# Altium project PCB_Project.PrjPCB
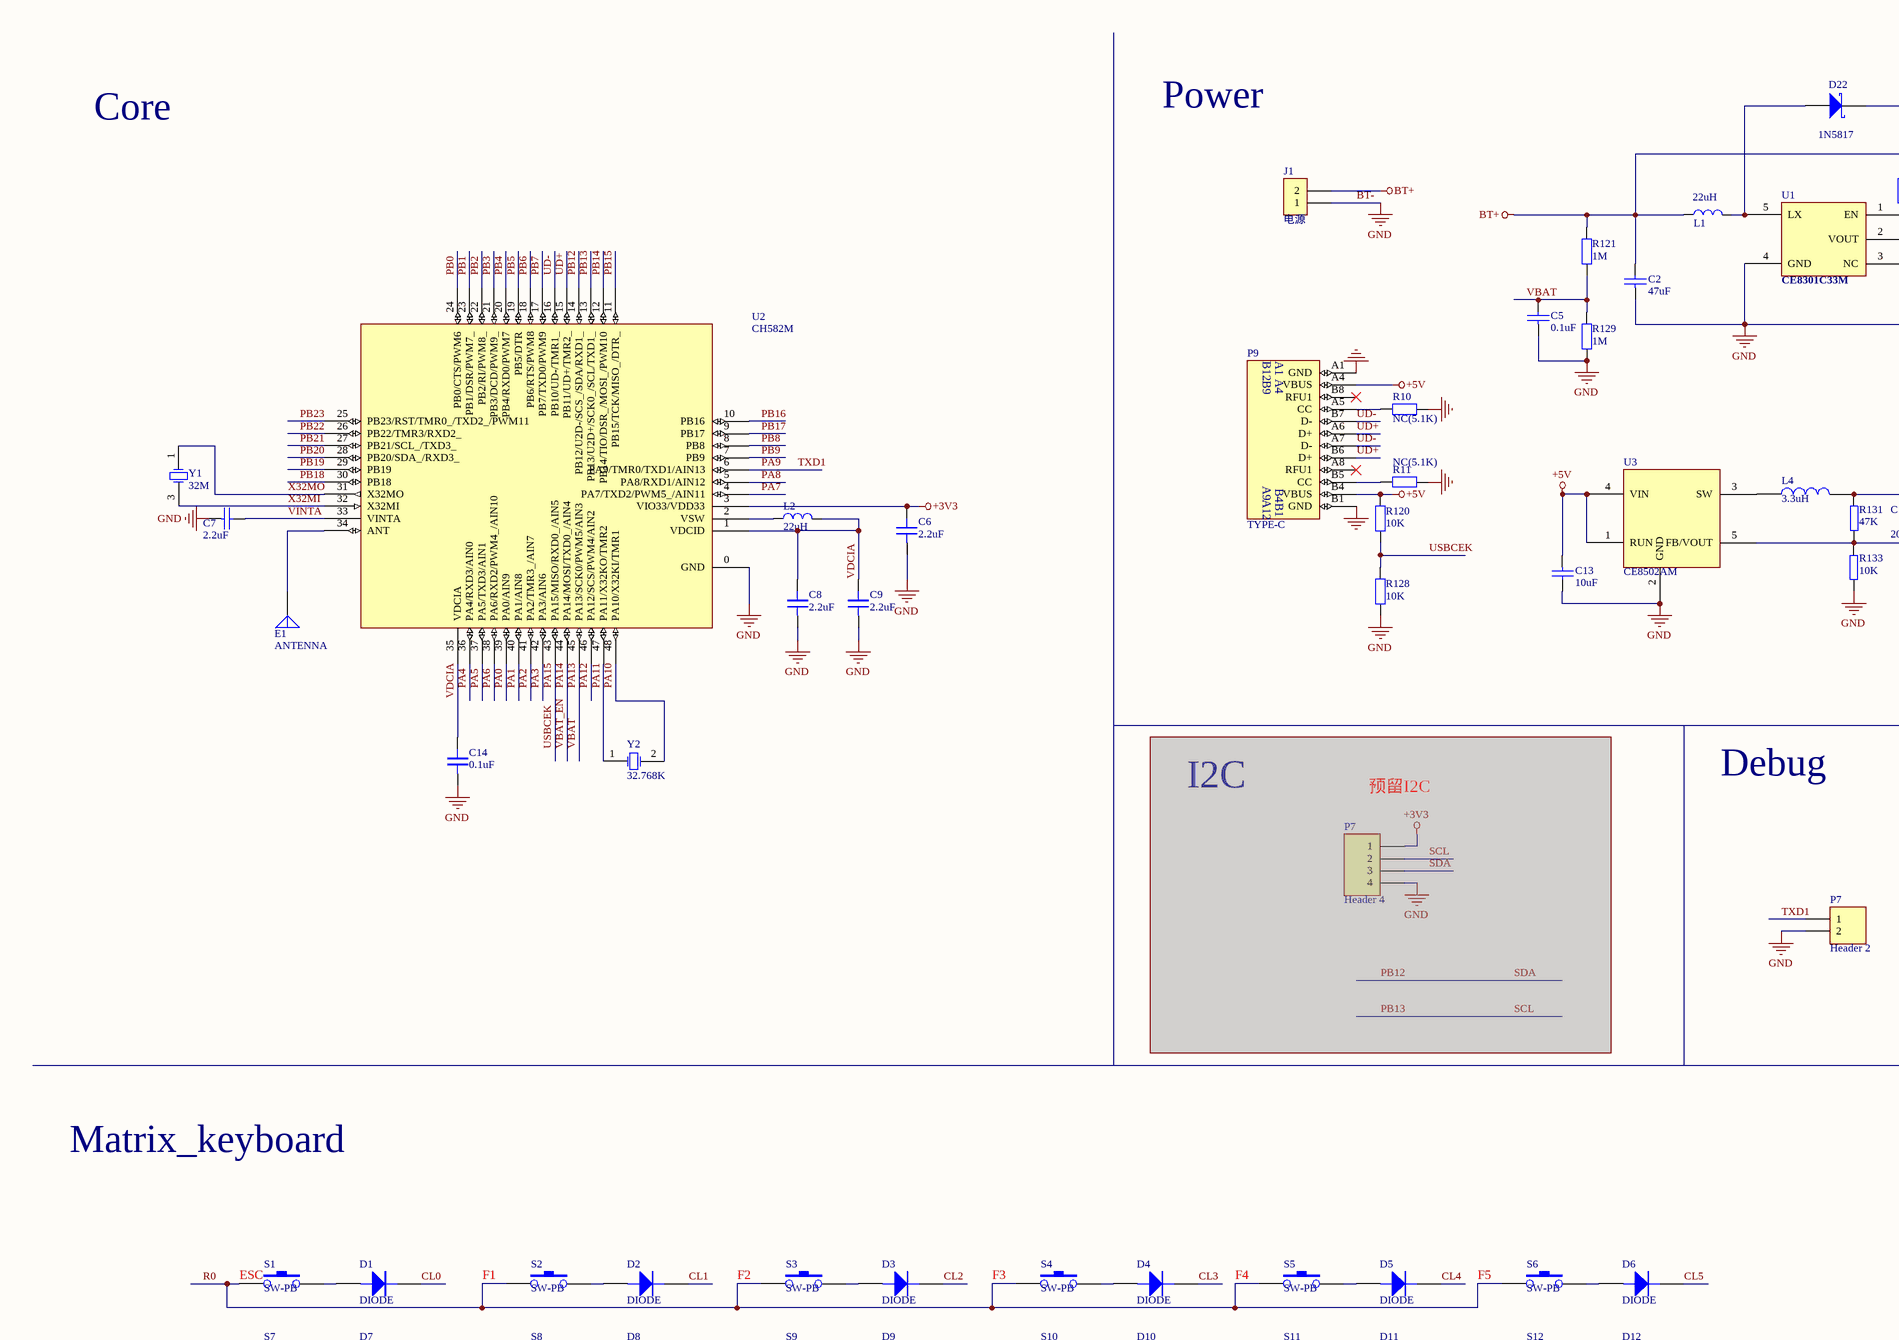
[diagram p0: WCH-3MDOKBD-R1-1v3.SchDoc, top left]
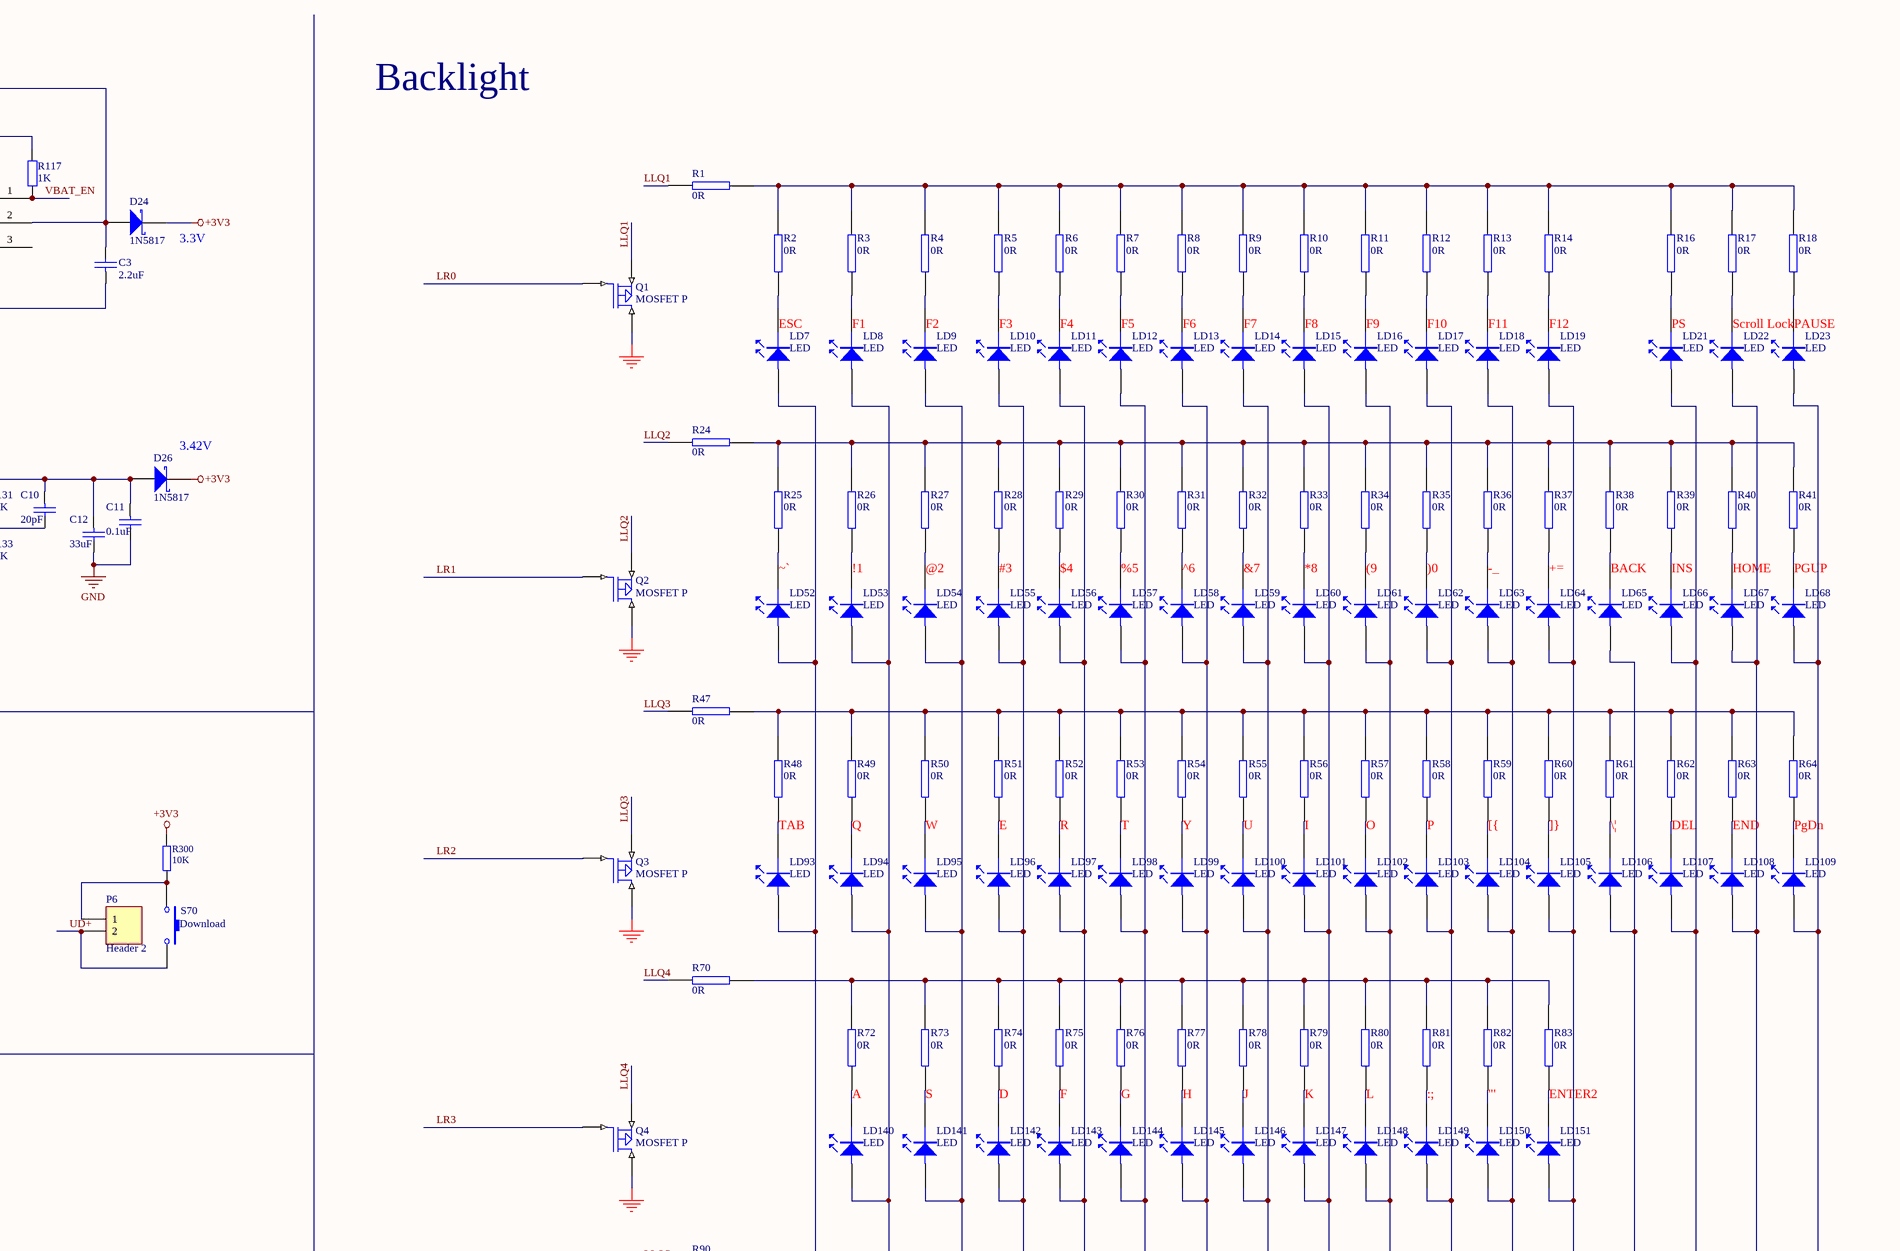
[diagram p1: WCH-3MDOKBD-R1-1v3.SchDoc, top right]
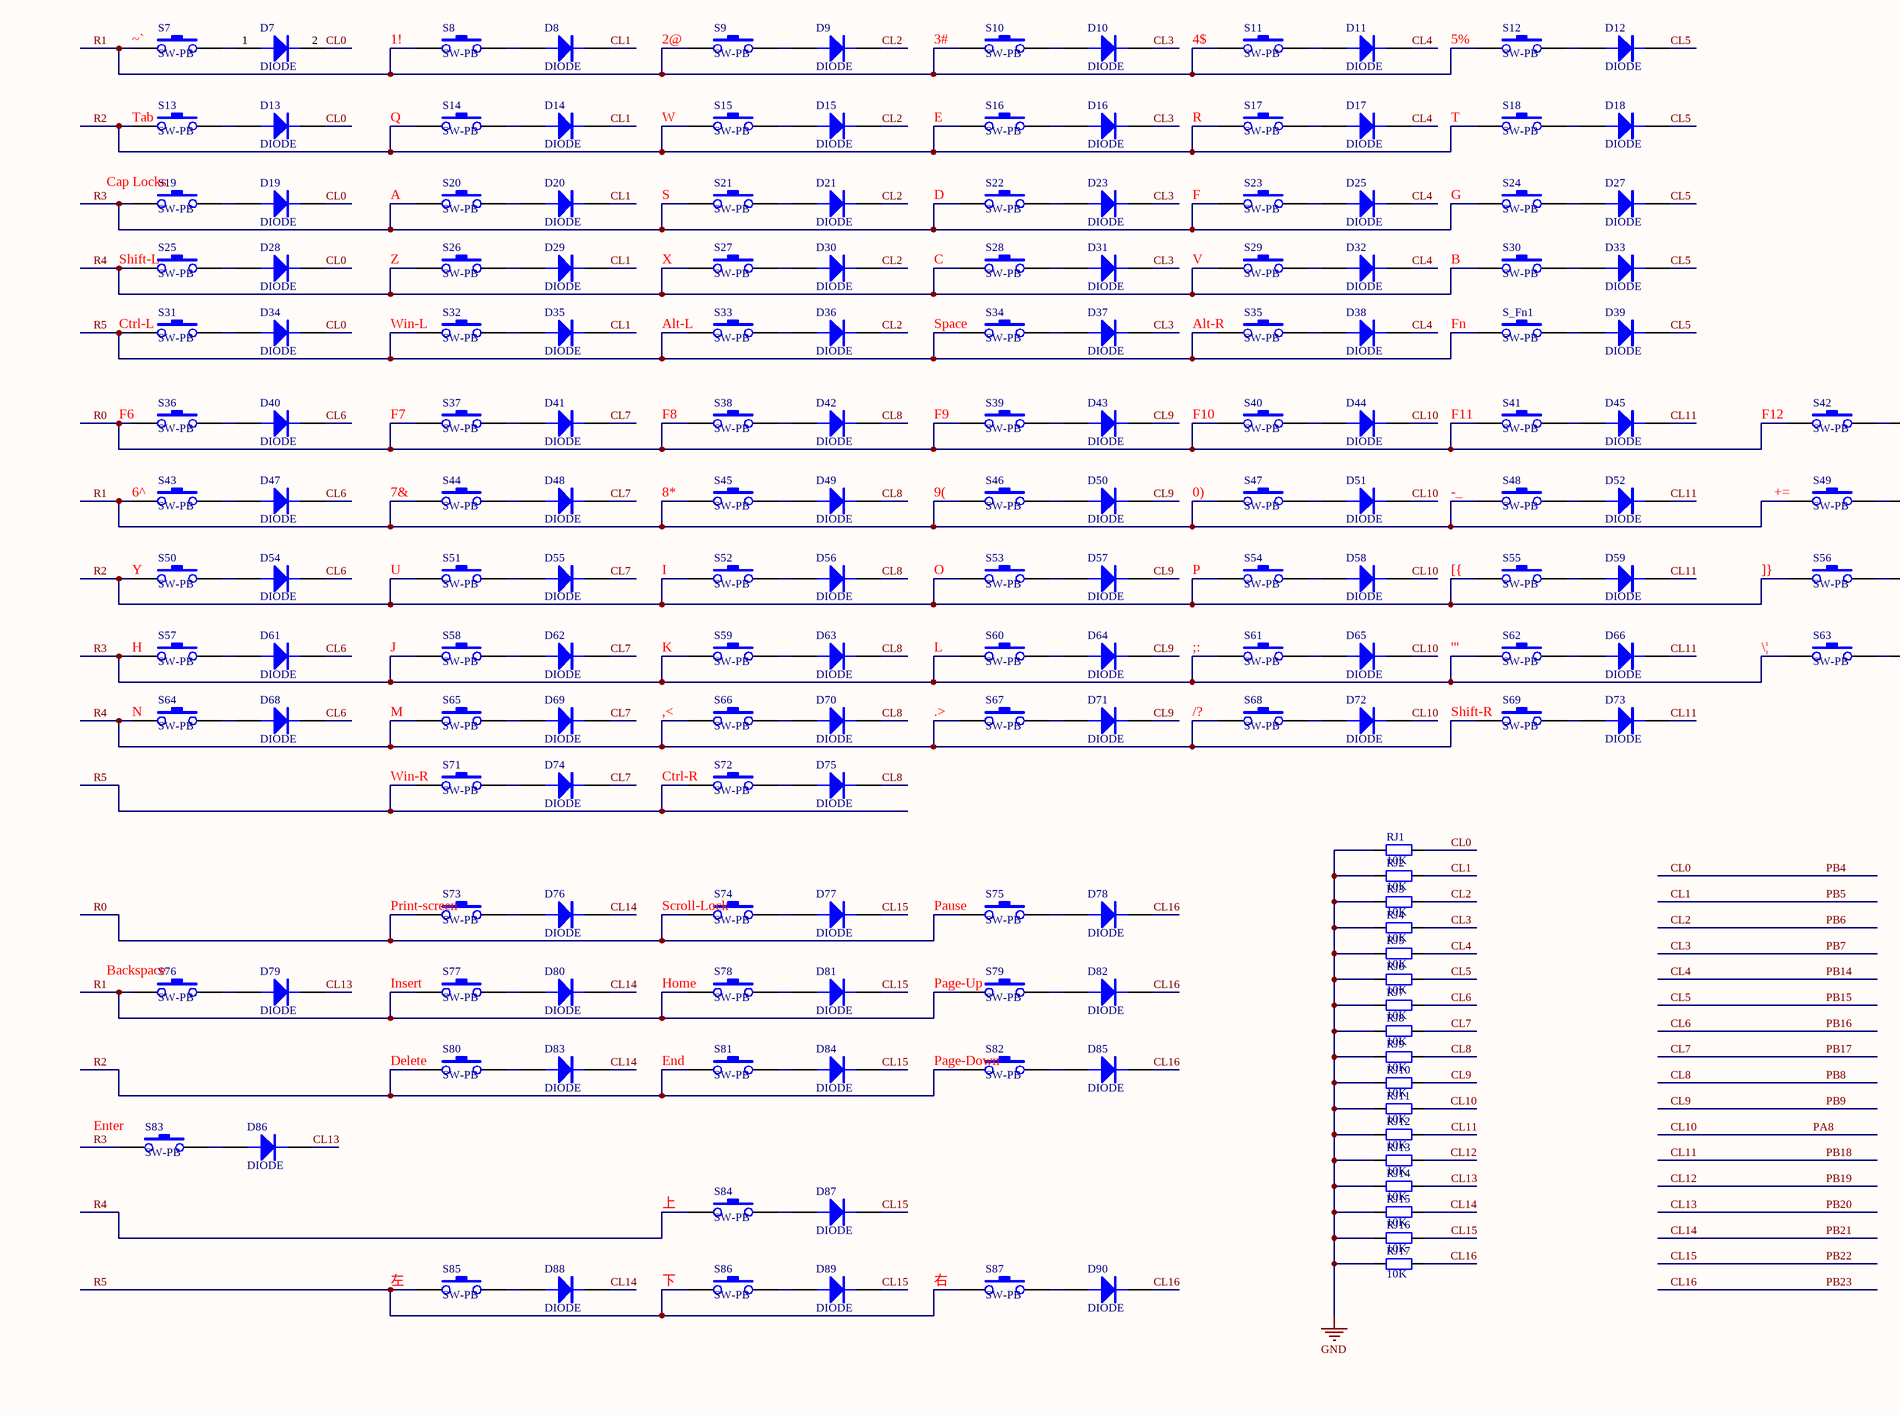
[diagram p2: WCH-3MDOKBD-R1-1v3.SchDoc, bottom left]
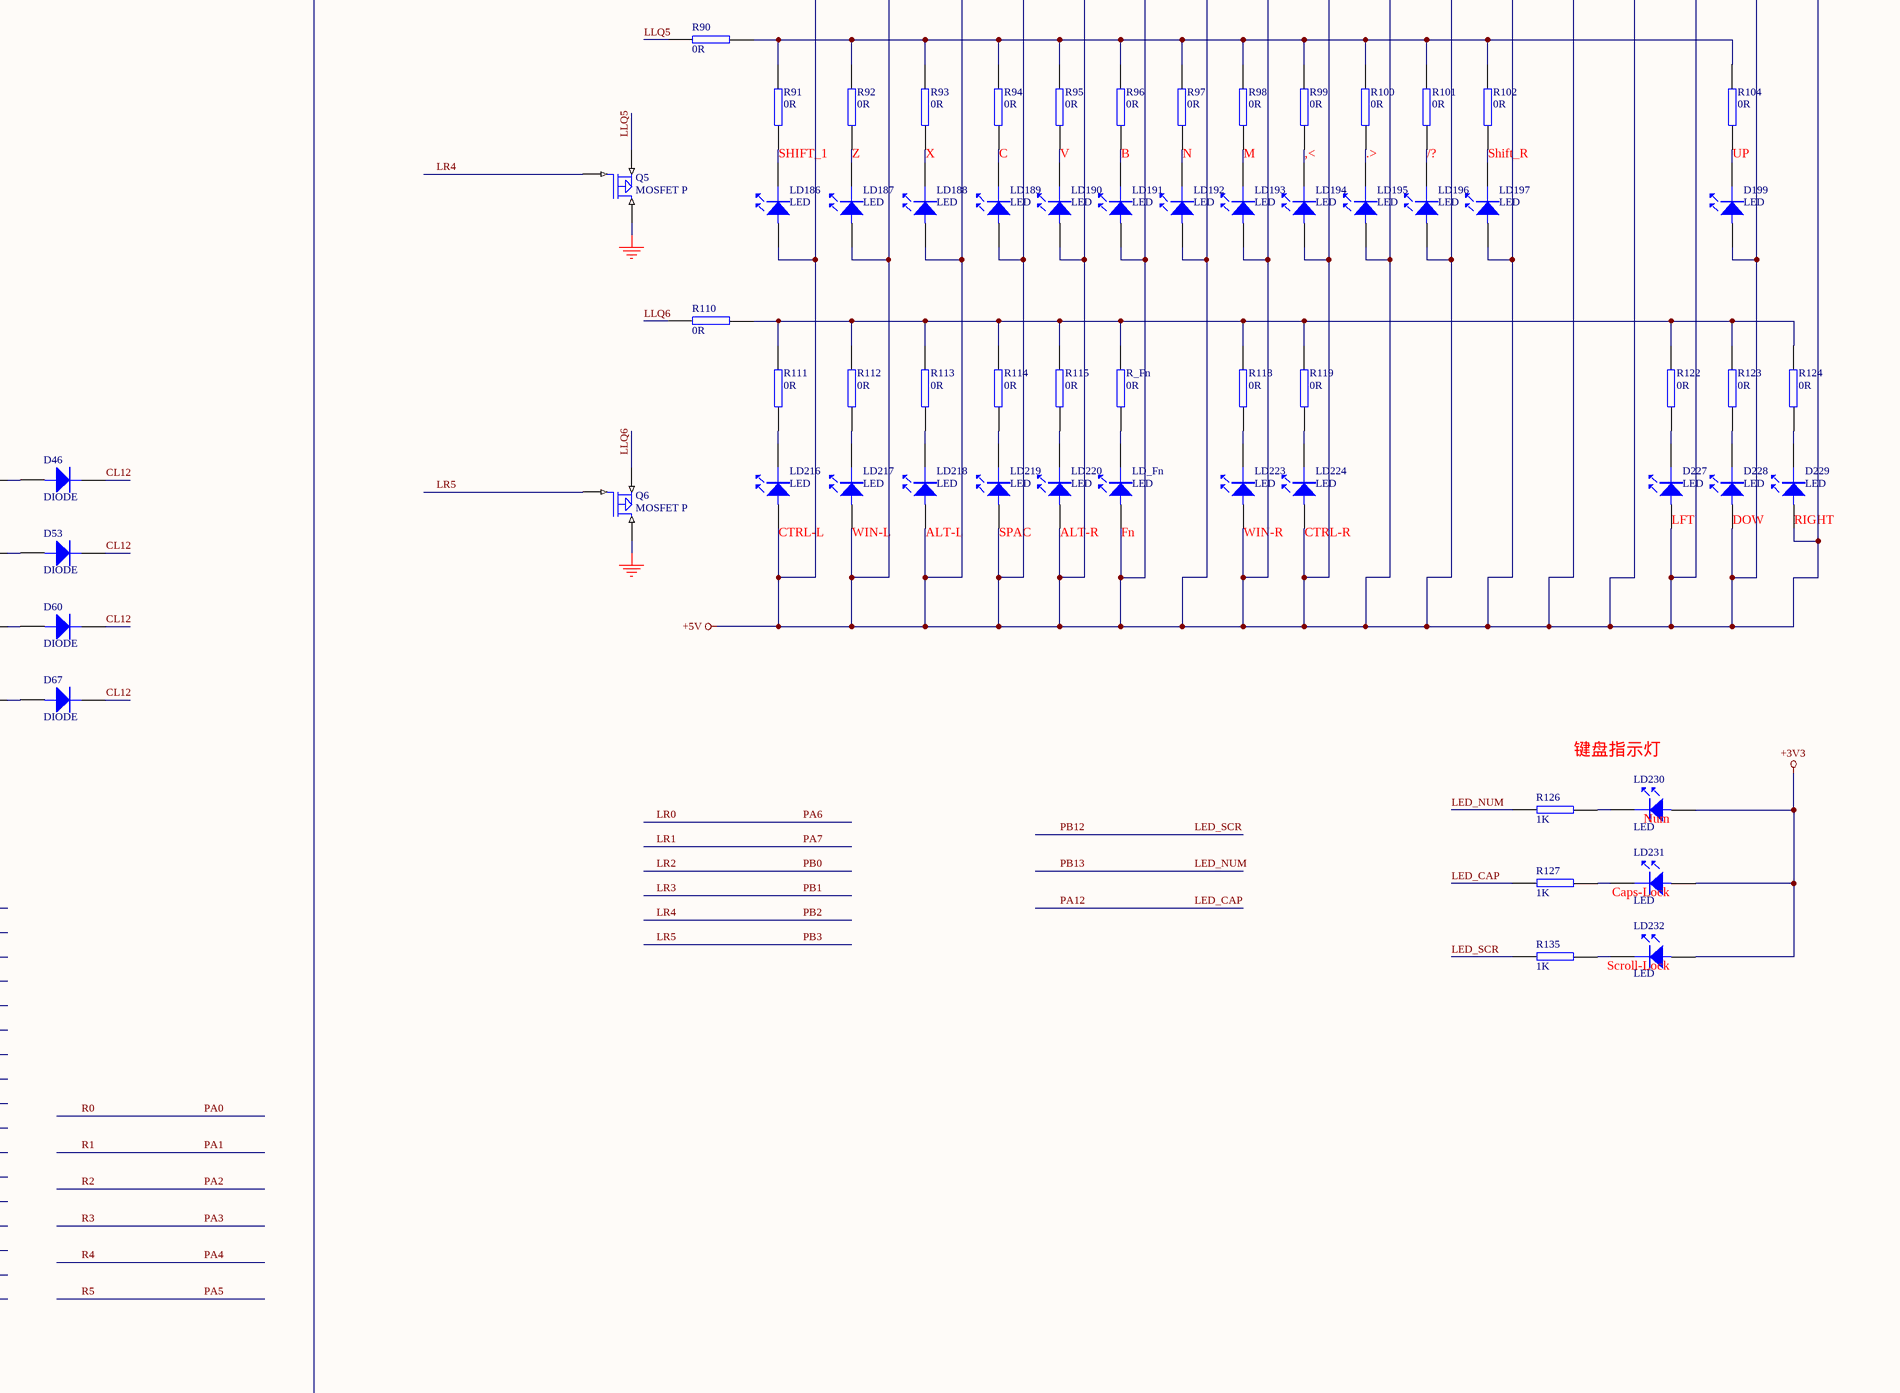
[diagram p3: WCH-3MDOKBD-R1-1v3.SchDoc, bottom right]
1 sheet, 421 parts. Net scope: global (net labels, ports and power ports of the same name join across sheets).
Board file: WCH-3MDOKBD-R1-1v3.PcbDoc

## Sheet WCH-3MDOKBD-R1-1v3.SchDoc
size A1

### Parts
(Parts that share a designator on the sheet are numbered #1, #2 ... from top to bottom, then left to right.)
C2  47uF  [3528_C]
C3  2.2uF  [0402_C]
C5  0.1uF  [0402_C]
C6  2.2uF  [0603_C]
C7  2.2uF  [0402_C]
C8  2.2uF  [0603_C]
C9  2.2uF  [0603_C]
C10  20pF  [0603_C]
C11  0.1uF  [0603_C]
C12  33uF  [3528_C]
C13  10uF  [3216_C]
C14  0.1uF  [0603_C]
D1  DIODE  [3216+]
D2  DIODE  [3216+]
D3  DIODE  [3216+]
D4  DIODE  [3216+]
D5  DIODE  [3216+]
D6  DIODE  [3216+]
D7  DIODE  [3216+]
D8  DIODE  [3216+]
D9  DIODE  [3216+]
D10  DIODE  [3216+]
D11  DIODE  [3216+]
D12  DIODE  [3216+]
D13  DIODE  [3216+]
D14  DIODE  [3216+]
D15  DIODE  [3216+]
D16  DIODE  [3216+]
D17  DIODE  [3216+]
D18  DIODE  [3216+]
D19  DIODE  [3216+]
D20  DIODE  [3216+]
D21  DIODE  [3216+]
D22  1N5817  [7227+]
D23  DIODE  [3216+]
D24  1N5817  [7227+]
D25  DIODE  [3216+]
D26  1N5817  [7227+]
D27  DIODE  [3216+]
D28  DIODE  [3216+]
D29  DIODE  [3216+]
D30  DIODE  [3216+]
D31  DIODE  [3216+]
D32  DIODE  [3216+]
D33  DIODE  [3216+]
D34  DIODE  [3216+]
D35  DIODE  [3216+]
D36  DIODE  [3216+]
D37  DIODE  [3216+]
D38  DIODE  [3216+]
D39  DIODE  [3216+]
D40  DIODE  [3216+]
D41  DIODE  [3216+]
D42  DIODE  [3216+]
D43  DIODE  [3216+]
D44  DIODE  [3216+]
D45  DIODE  [3216+]
D46  DIODE  [3216+]
D47  DIODE  [3216+]
D48  DIODE  [3216+]
D49  DIODE  [3216+]
D50  DIODE  [3216+]
D51  DIODE  [3216+]
D52  DIODE  [3216+]
D53  DIODE  [3216+]
D54  DIODE  [3216+]
D55  DIODE  [3216+]
D56  DIODE  [3216+]
D57  DIODE  [3216+]
D58  DIODE  [3216+]
D59  DIODE  [3216+]
D60  DIODE  [3216+]
D61  DIODE  [3216+]
D62  DIODE  [3216+]
D63  DIODE  [3216+]
D64  DIODE  [3216+]
D65  DIODE  [3216+]
D66  DIODE  [3216+]
D67  DIODE  [3216+]
D68  DIODE  [3216+]
D69  DIODE  [3216+]
D70  DIODE  [3216+]
D71  DIODE  [3216+]
D72  DIODE  [3216+]
D73  DIODE  [3216+]
D74  DIODE  [3216+]
D75  DIODE  [3216+]
D76  DIODE  [3216+]
D77  DIODE  [3216+]
D78  DIODE  [3216+]
D79  DIODE  [3216+]
D80  DIODE  [3216+]
D81  DIODE  [3216+]
D82  DIODE  [3216+]
D83  DIODE  [3216+]
D84  DIODE  [3216+]
D85  DIODE  [3216+]
D86  DIODE  [3216+]
D87  DIODE  [3216+]
D88  DIODE  [3216+]
D89  DIODE  [3216+]
D90  DIODE  [3216+]
D199  LED  [0603+]
D227  LED  [0603+]
D228  LED  [0603+]
D229  LED  [0603+]
E1  ANTENNA  [ANT-F-1-2.4G-1.6]
J1  电源  [SIP2-2.54mm]
L1  22uH  [SMD_7.3x7.8mm]
L2  22uH  [SMD_2x2mm]
L4  3.3uH  [SMD_5x5mm]
LD7  LED  [0603+]
LD8  LED  [0603+]
LD9  LED  [0603+]
LD10  LED  [0603+]
LD11  LED  [0603+]
LD12  LED  [0603+]
LD13  LED  [0603+]
LD14  LED  [0603+]
LD15  LED  [0603+]
LD16  LED  [0603+]
LD17  LED  [0603+]
LD18  LED  [0603+]
LD19  LED  [0603+]
LD21  LED  [0603+]
LD22  LED  [0603+]
LD23  LED  [0603+]
LD52  LED  [0603+]
LD53  LED  [0603+]
LD54  LED  [0603+]
LD55  LED  [0603+]
LD56  LED  [0603+]
LD57  LED  [0603+]
LD58  LED  [0603+]
LD59  LED  [0603+]
LD60  LED  [0603+]
LD61  LED  [0603+]
LD62  LED  [0603+]
LD63  LED  [0603+]
LD64  LED  [0603+]
LD65  LED  [0603+]
LD66  LED  [0603+]
LD67  LED  [0603+]
LD68  LED  [0603+]
LD93  LED  [0603+]
LD94  LED  [0603+]
LD95  LED  [0603+]
LD96  LED  [0603+]
LD97  LED  [0603+]
LD98  LED  [0603+]
LD99  LED  [0603+]
LD100  LED  [0603+]
LD101  LED  [0603+]
LD102  LED  [0603+]
LD103  LED  [0603+]
LD104  LED  [0603+]
LD105  LED  [0603+]
LD106  LED  [0603+]
LD107  LED  [0603+]
LD108  LED  [0603+]
LD109  LED  [0603+]
LD140  LED  [0603+]
LD141  LED  [0603+]
LD142  LED  [0603+]
LD143  LED  [0603+]
LD144  LED  [0603+]
LD145  LED  [0603+]
LD146  LED  [0603+]
LD147  LED  [0603+]
LD148  LED  [0603+]
LD149  LED  [0603+]
LD150  LED  [0603+]
LD151  LED  [0603+]
LD186  LED  [0603+]
LD187  LED  [0603+]
LD188  LED  [0603+]
LD189  LED  [0603+]
LD190  LED  [0603+]
LD191  LED  [0603+]
LD192  LED  [0603+]
LD193  LED  [0603+]
LD194  LED  [0603+]
LD195  LED  [0603+]
LD196  LED  [0603+]
LD197  LED  [0603+]
LD216  LED  [0603+]
LD217  LED  [0603+]
LD218  LED  [0603+]
LD219  LED  [0603+]
LD220  LED  [0603+]
LD223  LED  [0603+]
LD224  LED  [0603+]
LD230  LED  [0603+]
LD231  LED  [0603+]
LD232  LED  [0603+]
LD_Fn  LED  [0603+]
P6  Header 2  [SIP2-2.54mm]
P7#1  Header 4  [HDR1X4]  (masked out: inside a compile mask, not in the netlist)
P7#2  Header 2  [SIP2-2.54mm]
P9  TYPE-C  [TYPE-C-Receptacle-2.0]
Q1  MOSFET P  [SOT-23]
Q2  MOSFET P  [SOT-23]
Q3  MOSFET P  [SOT-23]
Q4  MOSFET P  [SOT-23]
Q5  MOSFET P  [SOT-23]
Q6  MOSFET P  [SOT-23]
R1  0R  [0603]
R2  0R  [0603]
R3  0R  [0603]
R4  0R  [0603]
R5  0R  [0603]
R6  0R  [0603]
R7  0R  [0603]
R8  0R  [0603]
R9  0R  [0603]
R10#1  0R  [0603]
R10#2  NC(5.1K)  [0603]
R11#1  0R  [0603]
R11#2  NC(5.1K)  [0603]
R12  0R  [0603]
R13  0R  [0603]
R14  0R  [0603]
R16  0R  [0603]
R17  0R  [0603]
R18  0R  [0603]
R24  0R  [0603]
R25  0R  [0603]
R26  0R  [0603]
R27  0R  [0603]
R28  0R  [0603]
R29  0R  [0603]
R30  0R  [0603]
R31  0R  [0603]
R32  0R  [0603]
R33  0R  [0603]
R34  0R  [0603]
R35  0R  [0603]
R36  0R  [0603]
R37  0R  [0603]
R38  0R  [0603]
R39  0R  [0603]
R40  0R  [0603]
R41  0R  [0603]
R47  0R  [0603]
R48  0R  [0603]
R49  0R  [0603]
R50  0R  [0603]
R51  0R  [0603]
R52  0R  [0603]
R53  0R  [0603]
R54  0R  [0603]
R55  0R  [0603]
R56  0R  [0603]
R57  0R  [0603]
R58  0R  [0603]
R59  0R  [0603]
R60  0R  [0603]
R61  0R  [0603]
R62  0R  [0603]
R63  0R  [0603]
R64  0R  [0603]
R70  0R  [0603]
R72  0R  [0603]
R73  0R  [0603]
R74  0R  [0603]
R75  0R  [0603]
R76  0R  [0603]
R77  0R  [0603]
R78  0R  [0603]
R79  0R  [0603]
R80  0R  [0603]
R81  0R  [0603]
R82  0R  [0603]
R83  0R  [0603]
R90  0R  [0603]
R91  0R  [0603]
R92  0R  [0603]
R93  0R  [0603]
R94  0R  [0603]
R95  0R  [0603]
R96  0R  [0603]
R97  0R  [0603]
R98  0R  [0603]
R99  0R  [0603]
R100  0R  [0603]
R101  0R  [0603]
R102  0R  [0603]
R104  0R  [0603]
R110  0R  [0603]
R111  0R  [0603]
R112  0R  [0603]
R113  0R  [0603]
R114  0R  [0603]
R115  0R  [0603]
R117  1K  [0603]
R118  0R  [0603]
R119  0R  [0603]
R120  10K  [0603]
R121  1M  [0603]
R122  0R  [0603]
R123  0R  [0603]
R124  0R  [0603]
R126  1K  [0603]
R127  1K  [0603]
R128  10K  [0603]
R129  1M  [0603]
R131  47K  [0603]
R133  10K  [0603]
R135  1K  [0603]
R300  10K  [0603]
R_Fn  0R  [0603]
RJ1  10K  [0603]
RJ2  10K  [0603]
RJ3  10K  [0603]
RJ4  10K  [0603]
RJ5  10K  [0603]
RJ6  10K  [0603]
RJ7  10K  [0603]
RJ8  10K  [0603]
RJ9  10K  [0603]
RJ10  10K  [0603]
RJ11  10K  [0603]
RJ12  10K  [0603]
RJ13  10K  [0603]
RJ14  10K  [0603]
RJ15  10K  [0603]
RJ16  10K  [0603]
RJ17  10K  [0603]
S1  SW-PB  [SMD_6.1x3.65x2.5mm-KEY]
S2  SW-PB  [SMD_6.1x3.65x2.5mm-KEY]
S3  SW-PB  [SMD_6.1x3.65x2.5mm-KEY]
S4  SW-PB  [SMD_6.1x3.65x2.5mm-KEY]
S5  SW-PB  [SMD_6.1x3.65x2.5mm-KEY]
S6  SW-PB  [SMD_6.1x3.65x2.5mm-KEY]
S7  SW-PB  [SMD_6.1x3.65x2.5mm-KEY]
S8  SW-PB  [SMD_6.1x3.65x2.5mm-KEY]
S9  SW-PB  [SMD_6.1x3.65x2.5mm-KEY]
S10  SW-PB  [SMD_6.1x3.65x2.5mm-KEY]
S11  SW-PB  [SMD_6.1x3.65x2.5mm-KEY]
S12  SW-PB  [SMD_6.1x3.65x2.5mm-KEY]
S13  SW-PB  [SMD_6.1x3.65x2.5mm-KEY]
S14  SW-PB  [SMD_6.1x3.65x2.5mm-KEY]
S15  SW-PB  [SMD_6.1x3.65x2.5mm-KEY]
S16  SW-PB  [SMD_6.1x3.65x2.5mm-KEY]
S17  SW-PB  [SMD_6.1x3.65x2.5mm-KEY]
S18  SW-PB  [SMD_6.1x3.65x2.5mm-KEY]
S19  SW-PB  [SMD_6.1x3.65x2.5mm-KEY]
S20  SW-PB  [SMD_6.1x3.65x2.5mm-KEY]
S21  SW-PB  [SMD_6.1x3.65x2.5mm-KEY]
S22  SW-PB  [SMD_6.1x3.65x2.5mm-KEY]
S23  SW-PB  [SMD_6.1x3.65x2.5mm-KEY]
S24  SW-PB  [SMD_6.1x3.65x2.5mm-KEY]
S25  SW-PB  [SMD_6.1x3.65x2.5mm-KEY]
S26  SW-PB  [SMD_6.1x3.65x2.5mm-KEY]
S27  SW-PB  [SMD_6.1x3.65x2.5mm-KEY]
S28  SW-PB  [SMD_6.1x3.65x2.5mm-KEY]
S29  SW-PB  [SMD_6.1x3.65x2.5mm-KEY]
S30  SW-PB  [SMD_6.1x3.65x2.5mm-KEY]
S31  SW-PB  [SMD_6.1x3.65x2.5mm-KEY]
S32  SW-PB  [SMD_6.1x3.65x2.5mm-KEY]
S33  SW-PB  [SMD_6.1x3.65x2.5mm-KEY]
S34  SW-PB  [SMD_6.1x3.65x2.5mm-KEY]
S35  SW-PB  [SMD_6.1x3.65x2.5mm-KEY]
S36  SW-PB  [SMD_6.1x3.65x2.5mm-KEY]
S37  SW-PB  [SMD_6.1x3.65x2.5mm-KEY]
S38  SW-PB  [SMD_6.1x3.65x2.5mm-KEY]
S39  SW-PB  [SMD_6.1x3.65x2.5mm-KEY]
S40  SW-PB  [SMD_6.1x3.65x2.5mm-KEY]
S41  SW-PB  [SMD_6.1x3.65x2.5mm-KEY]
S42  SW-PB  [SMD_6.1x3.65x2.5mm-KEY]
S43  SW-PB  [SMD_6.1x3.65x2.5mm-KEY]
S44  SW-PB  [SMD_6.1x3.65x2.5mm-KEY]
S45  SW-PB  [SMD_6.1x3.65x2.5mm-KEY]
S46  SW-PB  [SMD_6.1x3.65x2.5mm-KEY]
S47  SW-PB  [SMD_6.1x3.65x2.5mm-KEY]
S48  SW-PB  [SMD_6.1x3.65x2.5mm-KEY]
S49  SW-PB  [SMD_6.1x3.65x2.5mm-KEY]
S50  SW-PB  [SMD_6.1x3.65x2.5mm-KEY]
S51  SW-PB  [SMD_6.1x3.65x2.5mm-KEY]
S52  SW-PB  [SMD_6.1x3.65x2.5mm-KEY]
S53  SW-PB  [SMD_6.1x3.65x2.5mm-KEY]
S54  SW-PB  [SMD_6.1x3.65x2.5mm-KEY]
S55  SW-PB  [SMD_6.1x3.65x2.5mm-KEY]
S56  SW-PB  [SMD_6.1x3.65x2.5mm-KEY]
S57  SW-PB  [SMD_6.1x3.65x2.5mm-KEY]
S58  SW-PB  [SMD_6.1x3.65x2.5mm-KEY]
S59  SW-PB  [SMD_6.1x3.65x2.5mm-KEY]
S60  SW-PB  [SMD_6.1x3.65x2.5mm-KEY]
S61  SW-PB  [SMD_6.1x3.65x2.5mm-KEY]
S62  SW-PB  [SMD_6.1x3.65x2.5mm-KEY]
S63  SW-PB  [SMD_6.1x3.65x2.5mm-KEY]
S64  SW-PB  [SMD_6.1x3.65x2.5mm-KEY]
S65  SW-PB  [SMD_6.1x3.65x2.5mm-KEY]
S66  SW-PB  [SMD_6.1x3.65x2.5mm-KEY]
S67  SW-PB  [SMD_6.1x3.65x2.5mm-KEY]
S68  SW-PB  [SMD_6.1x3.65x2.5mm-KEY]
S69  SW-PB  [SMD_6.1x3.65x2.5mm-KEY]
S70  Download  [贴片按键]
S71  SW-PB  [SMD_6.1x3.65x2.5mm-KEY]
S72  SW-PB  [SMD_6.1x3.65x2.5mm-KEY]
S73  SW-PB  [SMD_6.1x3.65x2.5mm-KEY]
S74  SW-PB  [SMD_6.1x3.65x2.5mm-KEY]
S75  SW-PB  [SMD_6.1x3.65x2.5mm-KEY]
S76  SW-PB  [SMD_6.1x3.65x2.5mm-KEY]
S77  SW-PB  [SMD_6.1x3.65x2.5mm-KEY]
S78  SW-PB  [SMD_6.1x3.65x2.5mm-KEY]
S79  SW-PB  [SMD_6.1x3.65x2.5mm-KEY]
S80  SW-PB  [SMD_6.1x3.65x2.5mm-KEY]
S81  SW-PB  [SMD_6.1x3.65x2.5mm-KEY]
S82  SW-PB  [SMD_6.1x3.65x2.5mm-KEY]
S83  SW-PB  [SMD_6.1x3.65x2.5mm-KEY]
S84  SW-PB  [SMD_6.1x3.65x2.5mm-KEY]
S85  SW-PB  [SMD_6.1x3.65x2.5mm-KEY]
S86  SW-PB  [SMD_6.1x3.65x2.5mm-KEY]
S87  SW-PB  [SMD_6.1x3.65x2.5mm-KEY]
S_Fn1  SW-PB  [SMD_6.1x3.65x2.5mm-KEY]
U1  CE8301C33M  [SOT-23-5]
U2  CH582M  [QFN48_5X5]
U3  CE8502AM  [SOT-23-5]
Y1  32M  [XT3225]
Y2  32.768K  [FC-135]

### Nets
+3V3: C6.2 D24.2(K) D26.2(K) LD230.A LD231.A LD232.A R300.2 U2.3(VIO33/VDD33)
+5V: C13.1 D199.A D227.A D228.A D229.A LD7.A LD8.A LD9.A LD10.A LD11.A LD12.A LD13.A LD14.A LD15.A LD16.A LD17.A LD18.A LD19.A LD21.A LD22.A LD23.A LD52.A LD53.A LD54.A LD55.A LD56.A LD57.A LD58.A LD59.A LD60.A LD61.A LD62.A LD63.A LD64.A LD65.A LD66.A LD67.A LD68.A LD93.A LD94.A LD95.A LD96.A LD97.A LD98.A LD99.A LD100.A LD101.A LD102.A LD103.A LD104.A LD105.A LD106.A LD107.A LD108.A LD109.A LD140.A LD141.A LD142.A LD143.A LD144.A LD145.A LD146.A LD147.A LD148.A LD149.A LD150.A LD151.A LD186.A LD187.A LD188.A LD189.A LD190.A LD191.A LD192.A LD193.A LD194.A LD195.A LD196.A LD197.A LD216.A LD217.A LD218.A LD219.A LD220.A LD223.A LD224.A LD_Fn.A P9.A4(VBUS) P9.B4(VBUS) R120.2 U3.1(RUN) U3.4(VIN)
BT+: C2.2 J1.2 L1.1 R117.2 R121.2
BT-: C2.1 C3.1 C5.1 C6.1 C7.1 C8.1 C9.1 C11.2 C12.2 C13.2 C14.1 J1.1 P7#2.2 P9.A1(GND) P9.B1(GND) Q1.3(D) Q2.3(D) Q3.3(D) Q4.3(D) Q5.3(D) Q6.3(D) R10#2.2 R11#2.2 R128.1 R129.1 R133.1 RJ1.1 RJ2.1 RJ3.1 RJ4.1 RJ5.1 RJ6.1 RJ7.1 RJ8.1 RJ9.1 RJ10.1 RJ11.1 RJ12.1 RJ13.1 RJ14.1 RJ15.1 RJ16.1 RJ17.1 U1.4(GND) U2.0(GND) U3.2(GND)  [also labelled GND]
CL0: D1.2(K) D7.2(K) D13.2(K) D19.2(K) D28.2(K) D34.2(K) RJ1.2 U2.20(PB4/RXD0/PWM7)  [also labelled PB4]
CL1: D2.2(K) D8.2(K) D14.2(K) D20.2(K) D29.2(K) D35.2(K) RJ2.2 U2.19(PB5/DTR)  [also labelled PB5]
CL2: D3.2(K) D9.2(K) D15.2(K) D21.2(K) D30.2(K) D36.2(K) RJ3.2 U2.18(PB6/RTS/PWM8)  [also labelled PB6]
CL3: D4.2(K) D10.2(K) D16.2(K) D23.2(K) D31.2(K) D37.2(K) RJ4.2 U2.17(PB7/TXD0/PWM9)  [also labelled PB7]
CL4: D5.2(K) D11.2(K) D17.2(K) D25.2(K) D32.2(K) D38.2(K) RJ5.2 U2.12(PB14/TIO/DSR_/MOSI_/PWM10)  [also labelled PB14]
CL5: D6.2(K) D12.2(K) D18.2(K) D27.2(K) D33.2(K) D39.2(K) RJ6.2 U2.11(PB15/TCK/MISO_/DTR_)  [also labelled PB15]
CL6: D40.2(K) D47.2(K) D54.2(K) D61.2(K) D68.2(K) RJ7.2 U2.10(PB16)  [also labelled PB16]
CL7: D41.2(K) D48.2(K) D55.2(K) D62.2(K) D69.2(K) D74.2(K) RJ8.2 U2.9(PB17)  [also labelled PB17]
CL8: D42.2(K) D49.2(K) D56.2(K) D63.2(K) D70.2(K) D75.2(K) RJ9.2 U2.8(PB8)  [also labelled PB8]
CL9: D43.2(K) D50.2(K) D57.2(K) D64.2(K) D71.2(K) RJ10.2 U2.7(PB9)  [also labelled PB9]
CL10: D44.2(K) D51.2(K) D58.2(K) D65.2(K) D72.2(K) RJ11.2 U2.5(PA8/RXD1/AIN12)  [also labelled PA8]
CL11: D45.2(K) D52.2(K) D59.2(K) D66.2(K) D73.2(K) RJ12.2 U2.30(PB18)  [also labelled PB18]
CL12: D46.2(K) D53.2(K) D60.2(K) D67.2(K) RJ13.2 U2.29(PB19)  [also labelled PB19]
CL13: D79.2(K) D86.2(K) RJ14.2 U2.28(PB20/SDA_/RXD3_)  [also labelled PB20]
CL14: D76.2(K) D80.2(K) D83.2(K) D88.2(K) RJ15.2 U2.27(PB21/SCL_/TXD3_)  [also labelled PB21]
CL15: D77.2(K) D81.2(K) D84.2(K) D87.2(K) D89.2(K) RJ16.2 U2.26(PB22/TMR3/RXD2_)  [also labelled PB22]
CL16: D78.2(K) D82.2(K) D85.2(K) D90.2(K) RJ17.2 U2.25(PB23/RST/TMR0_/TXD2_/PWM11)  [also labelled PB23]
LED_CAP: R127.2 U2.46(PA12/SCS/PWM4/AIN2)  [also labelled PA12]
LED_NUM: R126.2 U2.13(PB13/U2D+/SCK0_/SCL/TXD1_)  [also labelled PB13]
LED_SCR: R135.2 U2.14(PB12/U2D-/SCS_/SDA/RXD1_)  [also labelled PB12]
LLQ1: Q1.2(S) R1.2
LLQ2: Q2.2(S) R24.2
LLQ3: Q3.2(S) R47.2
LLQ4: Q4.2(S) R70.2
LLQ5: Q5.2(S) R90.2
LLQ6: Q6.2(S) R110.2
LR0: Q1.1(G) U2.38(PA6/RXD2/PWM4_/AIN10)  [also labelled PA6]
LR1: Q2.1(G) U2.4(PA7/TXD2/PWM5_/AIN11)  [also labelled PA7]
LR2: Q3.1(G) U2.24(PB0/CTS/PWM6)  [also labelled PB0]
LR3: Q4.1(G) U2.23(PB1/DSR/PWM7_)  [also labelled PB1]
LR4: Q5.1(G) U2.22(PB2/RI/PWM8_)  [also labelled PB2]
LR5: Q6.1(G) U2.21(PB3/DCD/PWM9_)  [also labelled PB3]
PA0: S1.1 S2.1 S3.1 S4.1 S5.1 S6.1 S36.1 S37.1 S38.1 S39.1 S40.1 S41.1 S42.1 S73.1 S74.1 S75.1 U2.39(PA0/AIN9)  [also labelled R0]
PA1: S7.1 S8.1 S9.1 S10.1 S11.1 S12.1 S43.1 S44.1 S45.1 S46.1 S47.1 S48.1 S49.1 S76.1 S77.1 S78.1 S79.1 U2.40(PA1/AIN8)  [also labelled R1]
PA2: S13.1 S14.1 S15.1 S16.1 S17.1 S18.1 S50.1 S51.1 S52.1 S53.1 S54.1 S55.1 S56.1 S80.1 S81.1 S82.1 U2.41(PA2/TMR3_/AIN7)  [also labelled R2]
PA3: S19.1 S20.1 S21.1 S22.1 S23.1 S24.1 S57.1 S58.1 S59.1 S60.1 S61.1 S62.1 S63.1 S83.1 U2.42(PA3/AIN6)  [also labelled R3]
PA4: S25.1 S26.1 S27.1 S28.1 S29.1 S30.1 S64.1 S65.1 S66.1 S67.1 S68.1 S69.1 S84.1 U2.36(PA4/RXD3/AIN0)  [also labelled R4]
PA5: S31.1 S32.1 S33.1 S34.1 S35.1 S71.1 S72.1 S85.1 S86.1 S87.1 S_Fn1.1 U2.37(PA5/TXD3/AIN1)  [also labelled R5]
PA9: P7#2.1 U2.6(PA9/TMR0/TXD1/AIN13)  [also labelled TXD1]
PA10: U2.48(PA10/X32KI/TMR1) Y2.2(OSC2)
PA11: U2.47(PA11/X32KO/TMR2) Y2.1(OSC1)
PA13: C5.2 R121.1 R129.2 U2.45(PA13/SCK0/PWM5/AIN3)  [also labelled VBAT]
PA14: R117.1 U1.1(EN) U2.44(PA14/MOSI/TXD0_/AIN4)  [also labelled VBAT_EN]
PA15: R120.1 R128.2 U2.43(PA15/MISO/RXD0_/AIN5)  [also labelled USBCEK]
UD+: P6.2 P9.A6(D+) P9.B6(D+) S70.3 U2.15(PB11/UD+/TMR2_)
UD-: P9.A7(D-) P9.B7(D-) U2.16(PB10/UD-/TMR1_)
VDCIA: C8.2 C9.2 C14.2 L2.2 U2.1(VDCID) U2.35(VDCIA)
VINTA: C7.2 U2.33(VINTA)
X32MI: U2.32(X32MI) Y1.3(OSC2)
X32MO: U2.31(X32MO) Y1.1(OSC1)
NetC3_2: C3.2 D22.2(K) D24.1(A) U1.2(VOUT)
NetC10_1: C10.1 C11.1 C12.1 D26.1(A) L4.2 R131.1
NetC10_2: C10.2 R131.2 R133.2 U3.5(FB/VOUT)
NetD1_1: D1.1(A) S1.2
NetD2_1: D2.1(A) S2.2
NetD3_1: D3.1(A) S3.2
NetD4_1: D4.1(A) S4.2
NetD5_1: D5.1(A) S5.2
NetD6_1: D6.1(A) S6.2
NetD7_1: D7.1(A) S7.2
NetD8_1: D8.1(A) S8.2
NetD9_1: D9.1(A) S9.2
NetD10_1: D10.1(A) S10.2
NetD11_1: D11.1(A) S11.2
NetD12_1: D12.1(A) S12.2
NetD13_1: D13.1(A) S13.2
NetD14_1: D14.1(A) S14.2
NetD15_1: D15.1(A) S15.2
NetD16_1: D16.1(A) S16.2
NetD17_1: D17.1(A) S17.2
NetD18_1: D18.1(A) S18.2
NetD19_1: D19.1(A) S19.2
NetD20_1: D20.1(A) S20.2
NetD21_1: D21.1(A) S21.2
NetD22_1: D22.1(A) L1.2 U1.5(LX)
NetD23_1: D23.1(A) S22.2
NetD25_1: D25.1(A) S23.2
NetD27_1: D27.1(A) S24.2
NetD28_1: D28.1(A) S25.2
NetD29_1: D29.1(A) S26.2
NetD30_1: D30.1(A) S27.2
NetD31_1: D31.1(A) S28.2
NetD32_1: D32.1(A) S29.2
NetD33_1: D33.1(A) S30.2
NetD34_1: D34.1(A) S31.2
NetD35_1: D35.1(A) S32.2
NetD36_1: D36.1(A) S33.2
NetD37_1: D37.1(A) S34.2
NetD38_1: D38.1(A) S35.2
NetD39_1: D39.1(A) S_Fn1.2
NetD40_1: D40.1(A) S36.2
NetD41_1: D41.1(A) S37.2
NetD42_1: D42.1(A) S38.2
NetD43_1: D43.1(A) S39.2
NetD44_1: D44.1(A) S40.2
NetD45_1: D45.1(A) S41.2
NetD46_1: D46.1(A) S42.2
NetD47_1: D47.1(A) S43.2
NetD48_1: D48.1(A) S44.2
NetD49_1: D49.1(A) S45.2
NetD50_1: D50.1(A) S46.2
NetD51_1: D51.1(A) S47.2
NetD52_1: D52.1(A) S48.2
NetD53_1: D53.1(A) S49.2
NetD54_1: D54.1(A) S50.2
NetD55_1: D55.1(A) S51.2
NetD56_1: D56.1(A) S52.2
NetD57_1: D57.1(A) S53.2
NetD58_1: D58.1(A) S54.2
NetD59_1: D59.1(A) S55.2
NetD60_1: D60.1(A) S56.2
NetD61_1: D61.1(A) S57.2
NetD62_1: D62.1(A) S58.2
NetD63_1: D63.1(A) S59.2
NetD64_1: D64.1(A) S60.2
NetD65_1: D65.1(A) S61.2
NetD66_1: D66.1(A) S62.2
NetD67_1: D67.1(A) S63.2
NetD68_1: D68.1(A) S64.2
NetD69_1: D69.1(A) S65.2
NetD70_1: D70.1(A) S66.2
NetD71_1: D71.1(A) S67.2
NetD72_1: D72.1(A) S68.2
NetD73_1: D73.1(A) S69.2
NetD74_1: D74.1(A) S71.2
NetD75_1: D75.1(A) S72.2
NetD76_1: D76.1(A) S73.2
NetD77_1: D77.1(A) S74.2
NetD78_1: D78.1(A) S75.2
NetD79_1: D79.1(A) S76.2
NetD80_1: D80.1(A) S77.2
NetD81_1: D81.1(A) S78.2
NetD82_1: D82.1(A) S79.2
NetD83_1: D83.1(A) S80.2
NetD84_1: D84.1(A) S81.2
NetD85_1: D85.1(A) S82.2
NetD86_1: D86.1(A) S83.2
NetD87_1: D87.1(A) S84.2
NetD88_1: D88.1(A) S85.2
NetD89_1: D89.1(A) S86.2
NetD90_1: D90.1(A) S87.2
NetD199_K: D199.K R104.1
NetD227_K: D227.K R122.1
NetD228_K: D228.K R123.1
NetD229_K: D229.K R124.1
NetE1_1: E1.1(A) U2.34(ANT)
NetL2_1: L2.1 U2.2(VSW)
NetL4_1: L4.1 U3.3(SW)
NetLD7_K: LD7.K R2.1
NetLD8_K: LD8.K R3.1
NetLD9_K: LD9.K R4.1
NetLD10_K: LD10.K R5.1
NetLD11_K: LD11.K R6.1
NetLD12_K: LD12.K R7.1
NetLD13_K: LD13.K R8.1
NetLD14_K: LD14.K R9.1
NetLD15_K: LD15.K R10#1.1
NetLD16_K: LD16.K R11#1.1
NetLD17_K: LD17.K R12.1
NetLD18_K: LD18.K R13.1
NetLD19_K: LD19.K R14.1
NetLD21_K: LD21.K R16.1
NetLD22_K: LD22.K R17.1
NetLD23_K: LD23.K R18.1
NetLD52_K: LD52.K R25.1
NetLD53_K: LD53.K R26.1
NetLD54_K: LD54.K R27.1
NetLD55_K: LD55.K R28.1
NetLD56_K: LD56.K R29.1
NetLD57_K: LD57.K R30.1
NetLD58_K: LD58.K R31.1
NetLD59_K: LD59.K R32.1
NetLD60_K: LD60.K R33.1
NetLD61_K: LD61.K R34.1
NetLD62_K: LD62.K R35.1
NetLD63_K: LD63.K R36.1
NetLD64_K: LD64.K R37.1
NetLD65_K: LD65.K R38.1
NetLD66_K: LD66.K R39.1
NetLD67_K: LD67.K R40.1
NetLD68_K: LD68.K R41.1
NetLD93_K: LD93.K R48.1
NetLD94_K: LD94.K R49.1
NetLD95_K: LD95.K R50.1
NetLD96_K: LD96.K R51.1
NetLD97_K: LD97.K R52.1
NetLD98_K: LD98.K R53.1
NetLD99_K: LD99.K R54.1
NetLD100_K: LD100.K R55.1
NetLD101_K: LD101.K R56.1
NetLD102_K: LD102.K R57.1
NetLD103_K: LD103.K R58.1
NetLD104_K: LD104.K R59.1
NetLD105_K: LD105.K R60.1
NetLD106_K: LD106.K R61.1
NetLD107_K: LD107.K R62.1
NetLD108_K: LD108.K R63.1
NetLD109_K: LD109.K R64.1
NetLD140_K: LD140.K R72.1
NetLD141_K: LD141.K R73.1
NetLD142_K: LD142.K R74.1
NetLD143_K: LD143.K R75.1
NetLD144_K: LD144.K R76.1
NetLD145_K: LD145.K R77.1
NetLD146_K: LD146.K R78.1
NetLD147_K: LD147.K R79.1
NetLD148_K: LD148.K R80.1
NetLD149_K: LD149.K R81.1
NetLD150_K: LD150.K R82.1
NetLD151_K: LD151.K R83.1
NetLD186_K: LD186.K R91.1
NetLD187_K: LD187.K R92.1
NetLD188_K: LD188.K R93.1
NetLD189_K: LD189.K R94.1
NetLD190_K: LD190.K R95.1
NetLD191_K: LD191.K R96.1
NetLD192_K: LD192.K R97.1
NetLD193_K: LD193.K R98.1
NetLD194_K: LD194.K R99.1
NetLD195_K: LD195.K R100.1
NetLD196_K: LD196.K R101.1
NetLD197_K: LD197.K R102.1
NetLD216_K: LD216.K R111.1
NetLD217_K: LD217.K R112.1
NetLD218_K: LD218.K R113.1
NetLD219_K: LD219.K R114.1
NetLD220_K: LD220.K R115.1
NetLD223_K: LD223.K R118.1
NetLD224_K: LD224.K R119.1
NetLD230_K: LD230.K R126.1
NetLD231_K: LD231.K R127.1
NetLD232_K: LD232.K R135.1
NetLD_Fn_K: LD_Fn.K R_Fn.1
NetP6_1: P6.1 R300.1 S70.1
NetP9_A5: P9.A5(CC) R10#2.1
NetP9_B5: P9.B5(CC) R11#2.1
NetR1_1: R1.1 R2.2 R3.2 R4.2 R5.2 R6.2 R7.2 R8.2 R9.2 R10#1.2 R11#1.2 R12.2 R13.2 R14.2 R16.2 R17.2 R18.2
NetR24_1: R24.1 R25.2 R26.2 R27.2 R28.2 R29.2 R30.2 R31.2 R32.2 R33.2 R34.2 R35.2 R36.2 R37.2 R38.2 R39.2 R40.2 R41.2
NetR47_1: R47.1 R48.2 R49.2 R50.2 R51.2 R52.2 R53.2 R54.2 R55.2 R56.2 R57.2 R58.2 R59.2 R60.2 R61.2 R62.2 R63.2 R64.2
NetR70_1: R70.1 R72.2 R73.2 R74.2 R75.2 R76.2 R77.2 R78.2 R79.2 R80.2 R81.2 R82.2 R83.2
NetR90_1: R90.1 R91.2 R92.2 R93.2 R94.2 R95.2 R96.2 R97.2 R98.2 R99.2 R100.2 R101.2 R102.2 R104.2
NetR110_1: R110.1 R111.2 R112.2 R113.2 R114.2 R115.2 R118.2 R119.2 R122.2 R123.2 R124.2 R_Fn.2

Not connected (* = marked no-connect by the designer): P9 A8(RFU1)* B8(RFU1)*; U1 3(NC)

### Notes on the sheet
- Power
- Backlight
- Core
- (near D24) 3.3V
- (near LD7) ESC
- (near LD8) F1
- (near LD9) F2
- (near LD10) F3
- (near LD11) F4
- (near LD12) F5
- (near LD13) F6
- (near LD14) F7
- (near LD15) F8
- (near LD16) F9
- (near LD17) F10
- (near LD18) F11
- (near LD19) F12
- (near LD21) PS
- Scroll Lock
- (near LD23) PAUSE
- (near D26) 3.42V
- (near U3) Hot!!!
- (near LD52) ~`
- (near LD53) !1
- (near LD54) @2
- (near LD55) #3
- (near LD56) $4
- (near LD57) %5
- (near LD58) ^6
- (near LD59) &7
- (near LD60) *8
- (near LD61) (9
- (near LD62) )0
- (near LD63) -_
- (near LD64) +=
- (near LD65) BACK
- (near LD66) INS
- (near LD67) HOME
- (near LD68) PGUP
- Debug
- I2C
- 预留I2C
- TAB
- Q
- W
- E
- R
- T
- Y
- U
- I
- O
- P
- [{
- ]}
- \¦
- DEL
- END
- PgDn
- A
- S
- D
- F
- G
- H
- J
- K
- L
- :;
- "'
- ENTER2
- Matrix_keyboard
- (near S1) ESC
- (near S2) F1
- (near S3) F2
- (near S4) F3
- (near S5) F4
- (near S6) F5
- (near S7) ~`
- (near S8) 1!
- (near S9) 2@
- (near S10) 3#
- (near S11) 4$
- (near S12) 5%
- SHIFT_1
- Z
- X
- C
- V
- B
- N
- M
- ,<
- .>
- /?
- Shift_R
- UP
- (near S13) Tab
- (near S14) Q
- (near S15) W
- (near S16) E
- (near S19) Cap Locks
- (near S20) A
- (near S21) S
- (near S22) D
- (near S25) Shift-L
- (near S31) Ctrl-L
- (near S32) Win-L
- (near S33) Alt-L
- (near S34) Space
- (near S35) Alt-R
- (near S_Fn1) Fn
- (near S36) F6
- (near S37) F7
- (near S38) F8
- (near S39) F9
- (near S40) F10
- (near S41) F11
- (near S42) F12
- (near D227) LFT
- (near D228) DOW
- (near D229) RIGHT
- (near S43) 6^
- (near S44) 7&
- (near S45) 8*
- (near S46) 9(
- (near S47) 0)
- (near S48) -_
- (near S49) +=
- (near LD216) CTRL-L
- (near LD217) WIN-L
- (near LD218) ALT-L
- (near LD219) SPAC
- ALT-R
- (near LD_Fn) Fn
- WIN-R
- (near LD224) CTRL-R
- (near S50) Y
- (near S51) U
- (near S52) I
- (near S53) O
- (near S55) [{
- (near S56) ]}
- (near S57) H
- (near S58) J
- (near S59) K
- (near S60) L
- (near S61) ;:
- (near S62) '"
- (near S63) \¦
- (near S64) N
- (near S66) ,<
- (near S67) .>
- (near S68) /?
- (near S69) Shift-R
- 键盘指示灯
- (near S71) Win-R
- (near S72) Ctrl-R
- (near LD230) Num
- (near LD231) Caps-Lock
- (near S73) Print-screen
- (near S74) Scroll-Lock
- (near S75) Pause
- (near LD232) Scroll-Lock
- (near S76) Backspace
- (near S77) Insert
- (near S78) Home
- (near S79) Page-Up
- (near S80) Delete
- (near S81) End
- (near S82) Page-Down
- (near S83) Enter
- (near S84) 上
- (near S85) 左
- (near S86) 下
- (near S87) 右

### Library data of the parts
C2 C3 C5 C7 = C0402
C6 C8-C14 = CAP: Capacitor
D22 D24 D26 = D Schottky: Schottky Diode
E1 = ANTENNA: Generic Antenna
J1 = HDR1x2: Connector
L1 = 1.05.0226.04: 物料名称: 电感; Value2: 额定电流600mA; Value3: 顺络
L2 = INDUCTANCE
L4 = INDUCTOR
P6 P7#2 = Header 2: Header, 2-Pin
P7#1 = Header 4: Header, 4-Pin
P9 = TYPE-C1
R1-R9 R10#1 R11#1 R12-R14 R16-R18 R24-R41 R47-R64 R70 R72-R83 R90-R102 R104 R110-R115 R118 R119 R122-R124 R126 R127 R135 R_Fn = RES2
R10#2 R11#2 RJ1-RJ17 = Res2: Resistor
R117 R120 R121 R128 R129 = RES: Resistor
R131 R133 = R
R300 = DZ
S70 = SW-PB: Switch
U1 = 1.07.0021.05: 物料名称: IC
U2 = CH582M: RISC-V MCU with BLE/2*USB/ADC/PWM/SPI/I2C/4*UART
U3 = FP6160
Y1 Y2 = XTAL: Crystal Oscillator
